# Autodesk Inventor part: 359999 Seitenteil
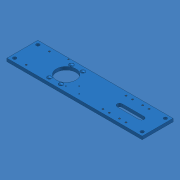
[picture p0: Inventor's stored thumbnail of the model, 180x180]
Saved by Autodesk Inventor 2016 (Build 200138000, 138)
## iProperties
Company: Mayer & Müller AG Schaltgeräte
Created: 2017-05
Part Number: 359999 Seitenteil
Material: 1.0120
Document SubType Name: Modeling
Designer: I.Baliuc
Manufacturer: Standard
Standards Organization: Custom
Description: Seitenteil, Trenner
Cost Center: 5,196 kg
Authority: 661896 mm^3
Density: 7.85 g/cm^3
Appearance: RAL 5012 Lichtblau
HalbzeugNorm: DIN 174
Zweck: HSLT / HSE - Standardseite
Abmessung: Fl. 120x12-170
SaveDate: 2006-10-28
SaveTime: 20:23
TotalMass: 5,196 kg
TotalVolume: 661896 mm^3
Kopiert_von_Autor: CH
Kopie_erstellt_am: 2017-05-01T12:58:19
Kopiert_von_Datei: D:\Inventor-Tools Tutorial\Bauteile\3\36\364835 Seitenteil.ipt
Kopie_Zieldatei: D:\Inventor-Tools Tutorial\Bauteile\3\35\359999 Seitenteil.ipt
Author: CH
Keywords: 380125
Revision Number: 364845
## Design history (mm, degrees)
sketch "Skizze2"
  geometry: L1 (-170, 60)-(355, 60); L2 (355, 60)-(355, -60); L3 (355, -60)-(-170, -60); L4 (-170, -60)-(-170, 60); L5 (-222.5, 0)-(512.5, 0) reference; L6 (0, -72)-(0, 96) reference; L7 (292.5, 10)-(207.5, 10); L8 (207.5, -10)-(292.5, -10); C1 r 38 at (0, 0); A1 r 10 centre (292.5, 0) between (292.5, -10) and (292.5, 10); A2 r 10 centre (207.5, 0) between (207.5, 10) and (207.5, -10)
  constraints: 12 end point, 4 point on circle, 4 point on line, 3 centre point, 3 parallel, 2 tangent, 1 horizontal, 1 perpendicular, 2 other
  dimensions: "d4" = 170 distance between parallel lines of L4 L6; "d5" = 525 distance of L1.start L1.end; "d6" = 120 distance of L3.end L1.start; "d7" = 76 diameter of C1; "d8" = 85 distance of A2.centre A1.centre; "d9" = 20 distance between parallel lines of L7 L8; "d10" = 62.5 distance from line of L2 A1.centre
extrude "Extrusion2" new body sketch "Skizze2" distance "d11" = 12; taper "d12" = 0 deg
sketch "Skizze3"
  geometry: L1 (355, 60)-(355, -60) reference; L2 (-170, -60)-(-170, 60) reference; L3 (-222.5, 0)-(512.5, 0) reference; 4 further points
  constraints: 2 symmetric about line
  dimensions: "d13" = 90 distance of point (-155, -45) point (-155, 45); "d14" = 15 distance from line of point (-155, 45) L2; "d15" = 90 distance of point (340, -45) point (340, 45) (= d13); "d16" = 15 distance from line of point (340, 45) L1 (= d14)
hole "Bohrung_Ø13" sketch "Skizze3" at (-155, 45), (-155, -45), (340, -45), (340, 45) diameter "d17" = 13; stored, may be unused: countersink angle "d21" = 90 deg, drill point angle "d23" = 118 deg; dims "d18" = 6, "d19" = 4, "d20" = 2, "d22" = 8
sketch "Skizze4"
  geometry: L1 (-222.5, 0)-(512.5, 0) reference; L2 (0, -72)-(0, 96) reference; 4 further points
  constraints: 3 symmetric about line
  dimensions: "d24" = 85 distance of point (22.5, -42.5) point (22.5, 42.5); "d25" = 45 distance of point (-22.5, 42.5) point (22.5, 42.5)
hole "Bohrung2" sketch "Skizze4" at (22.5, 42.5), (22.5, -42.5), (-22.5, -42.5), (-22.5, 42.5) diameter "d26" = 16.5; stored, may be unused: countersink angle "d30" = 90 deg, drill point angle "d32" = 0 deg; dims "d27" = 6, "d28" = 16.5, "d29" = 0.4, "d31" = 0.7
sketch "Skizze5"
  geometry: C1 r 8.25 at (0, 0) reference; C2 r 8.25 at (0, -85) reference; C3 r 8.25 at (45, -85) reference; C4 r 8.25 at (45, 0) reference; 4 further points
  constraints: 4 coincident
hole "Bohrung3" sketch "Skizze5" at (0, 0), (45, 0), (45, -85), (0, -85) diameter "d33" = 8.4; stored, may be unused: countersink angle "d37" = 90 deg, drill point angle "d39" = 118 deg; dims "d34" = 6, "d35" = 16.5 (= d26), "d36" = 2, "d38" = 8
sketch "Skizze6"
  geometry: L1 (-170, -60)-(-170, 60) reference; L2 (-222.5, 0)-(512.5, 0) reference; 2 further points
  constraints: 1 symmetric about line
  dimensions: "d40" = 90 distance of point (-110, -45) point (-110, 45); "d41" = 60 distance from line of point (-110, 45) L1
hole "Bohrung_M8_01" sketch "Skizze6" at (-110, 45), (-110, -45) diameter "d42" = 6.647; stored, may be unused: countersink angle "d46" = 90 deg, drill point angle "d48" = 118 deg; dims "d43" = 6, "d44" = 4, "d45" = 2, "d47" = 8
sketch "Skizze7"
  geometry: L1 (355, 60)-(355, -60) reference; L2 (-170, 60)-(355, 60) reference; L3 (-222.5, 0)-(512.5, 0) reference; 4 further points
  constraints: 1 horizontal, 1 vertical, 3 other
  dimensions: "d49" = 90 diameter of point (277, 45) L3; "d50" = 78 distance from line of L1 point (277, 45); "d53" = 90 distance of point (277, 45) point (277, -45) (= d49); "d56" = 25 distance of point (277, 45) point (252, 45)
hole "Bohrung_M8_02" sketch "Skizze7" at (277, 45), (277, -45), (252, 45), (252, -45) diameter "d59" = 6.647; stored, may be unused: countersink angle "d63" = 90 deg, drill point angle "d65" = 118 deg; dims "d60" = 6, "d61" = 4, "d62" = 2, "d64" = 8
hole "Bohrung_M6" diameter "d68" = 4.917; stored, may be unused: countersink angle "d72" = 90 deg, drill point angle "d74" = 118 deg; dims "d66" = 401, "d67" = 5, "d69" = 6, "d70" = 4, "d71" = 2, "d73" = 8
sketch "Skizze8"
  geometry: L1 (355, -60)-(-170, -60) reference; L2 (90.5, -40)-(38.5, -40); L3 (64.5, -14)-(64.5, -80.919); C1 r 38 at (0, 0) reference; 3 further points
  constraints: 4 end point, 3 coincident, 1 parallel, 1 perpendicular, 1 symmetric about line
  dimensions: "d75" = 26 distance from line of L3 point (38.5, -40); "d76" = 26 distance from line of L3 point (90.5, -40) (derived); "d77" = 26 distance from line of L2 point (64.5, -14); "d78" = 40 distance from line of L2 C1.centre; "d79" = 64.5 distance from line of L3 C1.centre
hole "Bohrung_M5" sketch "Skizze8" at (64.5, -14), (90.5, -40), (38.5, -40) diameter "d80" = 4.134; stored, may be unused: countersink angle "d84" = 90 deg, drill point angle "d86" = 118 deg; dims "d81" = 6, "d82" = 4, "d83" = 2, "d85" = 8
pattern_linear "Neue Bohrung (zusätzlich)" dims "d89" = 64.5
node "Center of Mass"
node "Volumenkörper1"
node "Volumenkörpern"
node "Oberflächenkörpern"
node "Projizierte Kontur1"
